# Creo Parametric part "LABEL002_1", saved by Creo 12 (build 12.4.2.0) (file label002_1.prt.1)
Units: Custom; MM, KILOGRAM, SECS

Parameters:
  PTC_WM_ITERATION = "0"
  PTC_WM_VERSION = "-.0"
  PTC_WM_LIFECYCLE_STATE = "In Work"
  PTC_WM_LIFECYCLE = "MO_CADDocument"
  PTC_WM_CREATED_BY = "Maximilian Roepper (Z0017RMS: MO)"
  PTC_WM_CREATED_ON = "18-Sep-26 11:36:42 AM"
  PTC_WM_MODIFIED_BY = "Maximilian Roepper (Z0017RMS: MO)"
  PTC_WM_MODIFIED_ON = "18-Sep-26 11:36:46 AM"
  PDMLINKNUMBER = "PDM000071455092"
  PTC_WM_NAME = "label002_1.prt"
  PTC_WM_NUMBER = "PDM000071455092"

Other parameters: WEIGHT, WEIGHT_FACTOR, WEIGHT_ADD, _MASS_TEMP, _DIFF_TEMP, MC_ERRORS, SUPPLIER

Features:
  1. coordinate system
  2. datum plane "PRT_YZ"
  3. datum plane "PRT_XY"
  4. datum plane "PRT_XZ"
  5. coordinate system
  6. datum axis
  7. datum axis
  8. datum axis
  9. coordinate system
  10. imported feature

Other named items: PRT, SIEMENS_MO, DRW_VIEW_ORG, PRT_X, PRT_Y, PRT_Z, CS0, ROUGH_GROB

Layers: 00_STD_CSYS-KSYS, 01_STD_PLANES-EBENEN, 02_STD_AXES-ACHSEN, 03_STD_CSYS-KSYS, 24_IMPORT_FEAT-IMPORT_KE

Surfaces: 6 plane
